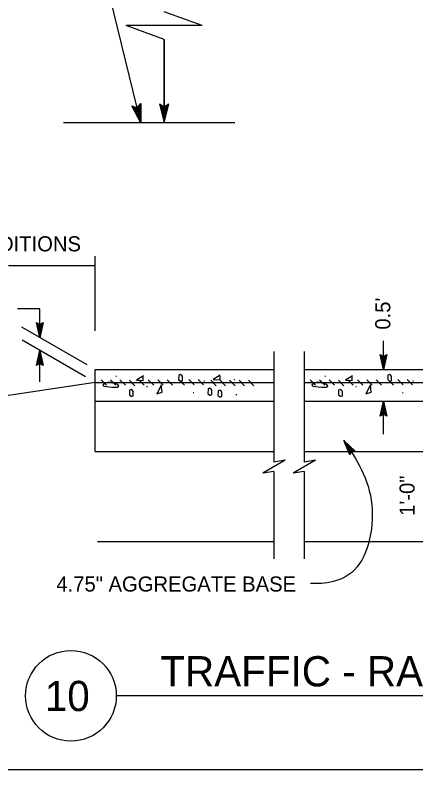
# Model space of a CAD drawing. Extents: x 6710407 to 6714861, y 1868090 to 1871317.
# Drawn here: x 6712808.6 to 6712967.7, y 1869155.1 to 1869454.7 of the extents above; entities that cross this region are included whole.
import ezdxf

# ---------------------------------------------------------------- set-up
doc = ezdxf.new("R2010")
doc.units = 0
for name, color, linetype in [('G-MARK', 7, 'Continuous'), ('G-TEXT', 7, 'Continuous'), ('G-TTLB-VIEW', 7, 'Continuous'), ('Nongeo Data(60)', 7, 'Continuous'), ('Sndwall Anno(59)', 7, 'Continuous')]:
    doc.layers.add(name, color=color, linetype=linetype)

# ---------------------------------------------------------------- blocks, each defined once
blk = doc.blocks.new('SHORTN')
at = {"layer": 'Sndwall Anno(59)'}
for p, q in [((-0.00193, 0), (-0.00259, 0.00447)), ((0.00264, -0.00447), (-0.00259, 0.00447)), ((-0.00193, 0), (-0.00193, 0)), ((0.00264, -0.00447), (0.00183, 0)), ((0.00183, 0), (0.00183, 0))]:
    blk.add_line(p, q, dxfattribs=at)

msp = doc.modelspace()

# ---------------------------------------------------------------- linework, layer by layer
at = {"layer": 'G-MARK'}
for p, q in [((6712858.43, 1869411.94), (6712844.63, 1869468.68)), ((6712882.78, 1869450.55), (6712867.73, 1869456.03)), ((6712882.78, 1869450.55), (6712852.68, 1869450.55)), ((6712867.73, 1869445.07), (6712852.68, 1869450.55)), ((6712867.73, 1869416.44), (6712867.73, 1869445.07)), ((6712895.84, 1869411.94), (6712827.82, 1869411.94)), ((6712840.41, 1869329.3), (6712840.41, 1869359.05)), ((6712805.88, 1869355.31), (6712840.41, 1869355.31)), ((6712818.41, 1869338.16), (6712809.58, 1869338.16)), ((6712818.41, 1869326.65), (6712818.41, 1869338.16)), ((6712837.19, 1869315.81), (6712811.24, 1869330.79)), ((6712836.45, 1869311.13), (6712811.35, 1869325.62)), ((6712954.78, 1869313.95), (6712954.78, 1869325.45)), ((6712818.41, 1869309.17), (6712818.41, 1869321.55)), ((6712911.34, 1869321.18), (6712911.34, 1869277.18)), ((6712923.37, 1869321.18), (6712923.37, 1869277.18)), ((6712954.78, 1869288.32), (6712954.78, 1869301.45)), ((6712911.34, 1869273.48), (6712911.34, 1869238.86)), ((6712923.37, 1869273.48), (6712923.37, 1869238.86)), ((6712841.25, 1869245.76), (6712911.34, 1869245.76)), ((6712923.4, 1869245.76), (6713088.4, 1869245.76))]:
    msp.add_line(p, q, dxfattribs=at)
msp.add_open_spline([(6712939.09, 1869285.79), (6712942.78, 1869280.42), (6712954.02, 1869264.09), (6712946.4, 1869228.42), (6712929.08, 1869228.94), (6712925.89, 1869229.03)], degree=3, dxfattribs=at)
at = {"layer": 'G-TEXT'}
for p, q in [((6712818.41, 1869326.65), (6712817.08, 1869332.65)), ((6712817.08, 1869332.65), (6712817.08, 1869332.65)), ((6712817.08, 1869332.65), (6712818.41, 1869331.85)), ((6712818.4, 1869328.04), (6712817.43, 1869332.42)), ((6712818.41, 1869329.42), (6712817.78, 1869332.24)), ((6712818.41, 1869330.8), (6712818.14, 1869332.01)), ((6712818.41, 1869331.85), (6712819.75, 1869332.65)), ((6712819.75, 1869332.65), (6712818.41, 1869326.65)), ((6712819.39, 1869332.44), (6712818.41, 1869328.03)), ((6712819.03, 1869332.2), (6712818.41, 1869329.42)), ((6712818.68, 1869332.03), (6712818.41, 1869330.8)), ((6712819.75, 1869332.65), (6712819.75, 1869332.65)), ((6712818.41, 1869326.65), (6712818.41, 1869326.65)), ((6712817.07, 1869315.55), (6712818.41, 1869321.55)), ((6712817.42, 1869315.76), (6712818.41, 1869320.17)), ((6712817.78, 1869316), (6712818.4, 1869318.78)), ((6712818.4, 1869318.78), (6712819.03, 1869315.96)), ((6712818.41, 1869321.55), (6712818.41, 1869321.55)), ((6712818.41, 1869321.55), (6712819.74, 1869315.55)), ((6712818.41, 1869320.16), (6712819.38, 1869315.78)), ((6712954.78, 1869313.95), (6712953.45, 1869319.95)), ((6712953.45, 1869319.95), (6712953.45, 1869319.95)), ((6712953.45, 1869319.95), (6712954.78, 1869319.15)), ((6712954.77, 1869315.34), (6712953.81, 1869319.72)), ((6712954.78, 1869316.71), (6712954.15, 1869319.54)), ((6712954.78, 1869318.1), (6712954.51, 1869319.3)), ((6712954.78, 1869319.15), (6712956.12, 1869319.95)), ((6712956.12, 1869319.95), (6712954.78, 1869313.95)), ((6712955.76, 1869319.73), (6712954.78, 1869315.33)), ((6712955.4, 1869319.5), (6712954.78, 1869316.71)), ((6712955.05, 1869319.32), (6712954.78, 1869318.1)), ((6712956.12, 1869319.95), (6712956.12, 1869319.95)), ((6712818.41, 1869316.35), (6712817.07, 1869315.55)), ((6712818.13, 1869316.17), (6712818.4, 1869317.4)), ((6712818.4, 1869317.4), (6712818.67, 1869316.19)), ((6712819.74, 1869315.55), (6712818.41, 1869316.35)), ((6712817.07, 1869315.55), (6712817.07, 1869315.55)), ((6712819.74, 1869315.55), (6712819.74, 1869315.55)), ((6712954.78, 1869313.95), (6712954.78, 1869313.95)), ((6712953.44, 1869295.45), (6712954.78, 1869301.45)), ((6712954.78, 1869301.45), (6712954.78, 1869301.45)), ((6712954.78, 1869301.45), (6712956.11, 1869295.45)), ((6712953.79, 1869295.67), (6712954.78, 1869300.07)), ((6712954.15, 1869295.9), (6712954.77, 1869298.69)), ((6712954.77, 1869298.69), (6712955.4, 1869295.86)), ((6712954.78, 1869300.06), (6712955.75, 1869295.69)), ((6712954.78, 1869296.25), (6712953.44, 1869295.45)), ((6712953.44, 1869295.45), (6712953.44, 1869295.45)), ((6712954.5, 1869296.08), (6712954.77, 1869297.31)), ((6712954.77, 1869297.31), (6712955.04, 1869296.1)), ((6712956.11, 1869295.45), (6712954.78, 1869296.25)), ((6712956.11, 1869295.45), (6712956.11, 1869295.45)), ((6712941.39, 1869280.09), (6712939.09, 1869285.79)), ((6712939.09, 1869285.79), (6712939.09, 1869285.79)), ((6712939.09, 1869285.79), (6712943.59, 1869281.6)), ((6712941.56, 1869280.47), (6712939.87, 1869284.65)), ((6712939.88, 1869284.64), (6712943.16, 1869281.59)), ((6712941.72, 1869280.86), (6712940.65, 1869283.51)), ((6712940.65, 1869283.51), (6712942.77, 1869281.54)), ((6712942.04, 1869281.5), (6712941.39, 1869280.09)), ((6712941.39, 1869280.09), (6712941.39, 1869280.09)), ((6712941.91, 1869281.2), (6712941.44, 1869282.37)), ((6712941.44, 1869282.37), (6712942.34, 1869281.53)), ((6712943.59, 1869281.6), (6712942.04, 1869281.5)), ((6712943.59, 1869281.6), (6712943.59, 1869281.6))]:
    msp.add_line(p, q, dxfattribs=at)
for points in [[(6712858.43, 1869411.94), (6712854.87, 1869418.7), (6712856.97, 1869417.94), (6712858.48, 1869419.58), (6712858.43, 1869411.94)], [(6712858.43, 1869411.94), (6712854.87, 1869418.7), (6712856.97, 1869417.94), (6712858.48, 1869419.58), (6712858.43, 1869411.94)], [(6712858.12, 1869413.22), (6712855.54, 1869418.12), (6712857.06, 1869417.57), (6712858.15, 1869418.75), (6712858.12, 1869413.22)], [(6712858.12, 1869413.22), (6712855.54, 1869418.12), (6712857.06, 1869417.57), (6712858.15, 1869418.75), (6712858.12, 1869413.22)], [(6712857.86, 1869414.29), (6712856.1, 1869417.63), (6712857.14, 1869417.25), (6712857.89, 1869418.06), (6712857.86, 1869414.29)], [(6712857.86, 1869414.29), (6712856.1, 1869417.63), (6712857.14, 1869417.25), (6712857.89, 1869418.06), (6712857.86, 1869414.29)], [(6712867.73, 1869411.94), (6712869.58, 1869419.35), (6712867.73, 1869418.12), (6712865.87, 1869419.35), (6712867.73, 1869411.94)], [(6712867.73, 1869411.94), (6712869.58, 1869419.35), (6712867.73, 1869418.12), (6712865.87, 1869419.35), (6712867.73, 1869411.94)], [(6712867.73, 1869413.25), (6712869.07, 1869418.62), (6712867.73, 1869417.73), (6712866.38, 1869418.62), (6712867.73, 1869413.25)], [(6712867.73, 1869413.25), (6712869.07, 1869418.62), (6712867.73, 1869417.73), (6712866.38, 1869418.62), (6712867.73, 1869413.25)], [(6712867.73, 1869414.36), (6712868.65, 1869418.01), (6712867.73, 1869417.4), (6712866.81, 1869418.01), (6712867.73, 1869414.36)], [(6712867.73, 1869414.36), (6712868.65, 1869418.01), (6712867.73, 1869417.4), (6712866.81, 1869418.01), (6712867.73, 1869414.36)], [(6712857.64, 1869415.17), (6712856.56, 1869417.22), (6712857.2, 1869417), (6712857.66, 1869417.49), (6712857.64, 1869415.17)], [(6712857.64, 1869415.17), (6712856.56, 1869417.22), (6712857.2, 1869417), (6712857.66, 1869417.49), (6712857.64, 1869415.17)], [(6712857.85, 1869415.28), (6712857.05, 1869416.8), (6712857.26, 1869416.72), (6712857.42, 1869416.89), (6712857.4, 1869415.17)], [(6712857.85, 1869415.28), (6712857.05, 1869416.8), (6712857.26, 1869416.72), (6712857.42, 1869416.89), (6712857.4, 1869415.17)], [(6712867.73, 1869415.27), (6712868.3, 1869417.52), (6712867.73, 1869417.15), (6712867.16, 1869417.52), (6712867.73, 1869415.27)], [(6712867.73, 1869415.27), (6712868.3, 1869417.52), (6712867.73, 1869417.15), (6712867.16, 1869417.52), (6712867.73, 1869415.27)], [(6712867.5, 1869415.32), (6712867.92, 1869416.98), (6712867.73, 1869416.86), (6712867.54, 1869416.98), (6712867.96, 1869415.32)], [(6712867.5, 1869415.32), (6712867.92, 1869416.98), (6712867.73, 1869416.86), (6712867.54, 1869416.98), (6712867.96, 1869415.32)]]:
    msp.add_lwpolyline(points, dxfattribs=at)
at = {"layer": 'G-TTLB-VIEW'}
msp.add_lwpolyline([(6711433.78, 1870605.06), (6713227.53, 1870605.06), (6713227.53, 1869155.06), (6711433.78, 1869155.06)], close=True, dxfattribs=at)
at = {"layer": 'Nongeo Data(60)'}
for p, q in [((6712867.73, 1869445.07), (6712867.73, 1869411.94)), ((6712840.41, 1869313.95), (6712911.34, 1869313.95)), ((6712840.41, 1869281.45), (6712840.41, 1869313.95)), ((6712923.4, 1869313.95), (6713088.4, 1869313.95)), ((6712844.83, 1869307.79), (6712842.69, 1869309.93)), ((6712848.58, 1869307.79), (6712846.44, 1869309.93)), ((6712848.54, 1869311.4), (6712848.82, 1869311.4)), ((6712852.33, 1869307.79), (6712850.19, 1869309.93)), ((6712859.83, 1869307.79), (6712857.69, 1869309.93)), ((6712863.58, 1869307.79), (6712861.44, 1869309.93)), ((6712867.33, 1869307.79), (6712865.19, 1869309.93)), ((6712871.08, 1869307.79), (6712868.94, 1869309.93)), ((6712875.86, 1869307.73), (6712873.72, 1869309.87)), ((6712879.61, 1869307.93), (6712877.47, 1869310.07)), ((6712883.36, 1869307.93), (6712881.22, 1869310.07)), ((6712895.47, 1869310.09), (6712895.75, 1869310.09)), ((6712927.83, 1869307.79), (6712925.69, 1869309.93)), ((6712931.58, 1869307.79), (6712929.44, 1869309.93)), ((6712931.53, 1869311.4), (6712931.81, 1869311.4)), ((6712935.33, 1869307.79), (6712933.19, 1869309.93)), ((6712942.83, 1869307.79), (6712940.69, 1869309.93)), ((6712946.58, 1869307.79), (6712944.44, 1869309.93)), ((6712950.33, 1869307.79), (6712948.19, 1869309.93)), ((6712954.08, 1869307.79), (6712951.94, 1869309.93)), ((6712958.85, 1869307.73), (6712956.71, 1869309.87)), ((6712962.6, 1869307.93), (6712960.46, 1869310.07)), ((6712966.35, 1869307.93), (6712964.21, 1869310.07)), ((6712840.37, 1869308.86), (6712755.29, 1869296.08)), ((6712840.37, 1869308.86), (6712911.34, 1869308.86)), ((6712856.08, 1869307.59), (6712853.94, 1869309.73)), ((6712860.79, 1869307.22), (6712861.07, 1869307.22)), ((6712883.48, 1869309.57), (6712883.76, 1869309.57)), ((6712888.37, 1869307.59), (6712886.23, 1869309.73)), ((6712892.12, 1869307.59), (6712889.98, 1869309.73)), ((6712895.87, 1869307.59), (6712893.73, 1869309.73)), ((6712899.62, 1869307.59), (6712897.48, 1869309.73)), ((6712903.37, 1869307.59), (6712901.23, 1869309.73)), ((6712923.37, 1869308.86), (6713088.5, 1869308.86)), ((6712939.08, 1869307.59), (6712936.94, 1869309.73)), ((6712943.79, 1869307.22), (6712944.07, 1869307.22)), ((6712966.47, 1869309.57), (6712966.75, 1869309.57)), ((6712879.3, 1869304.87), (6712879.58, 1869304.87)), ((6712896.25, 1869304.09), (6712896.53, 1869304.09)), ((6712962.3, 1869304.87), (6712962.58, 1869304.87)), ((6712840.41, 1869301.45), (6712911.34, 1869301.45)), ((6712923.4, 1869301.45), (6713088.4, 1869301.45)), ((6712840.41, 1869281.45), (6712911.34, 1869281.45)), ((6712923.4, 1869281.45), (6713088.4, 1869281.45)), ((6713173.03, 1869184.48), (6712848.73, 1869184.48))]:
    msp.add_line(p, q, dxfattribs=at)
for points in [[(6712859.52, 1869311.48), (6712856.72, 1869309.76), (6712859.4, 1869309.64), (6712859.4, 1869311.15)], [(6712873.53, 1869311.52), (6712873.47, 1869309.99), (6712874.19, 1869309.37), (6712874.54, 1869309.37), (6712875.04, 1869309.55), (6712875.04, 1869310.27), (6712875.04, 1869311.23), (6712874.76, 1869311.68), (6712874.14, 1869312.06), (6712873.53, 1869311.79), (6712873.53, 1869311.52), (6712873.53, 1869311.52)], [(6712890.03, 1869311.74), (6712887.23, 1869310.02), (6712889.91, 1869309.9), (6712889.91, 1869311.41)], [(6712942.52, 1869311.48), (6712939.72, 1869309.76), (6712942.4, 1869309.64), (6712942.4, 1869311.15)], [(6712956.53, 1869311.52), (6712956.47, 1869309.99), (6712957.19, 1869309.37), (6712957.54, 1869309.37), (6712958.04, 1869309.55), (6712958.04, 1869310.27), (6712958.04, 1869311.23), (6712957.76, 1869311.68), (6712957.14, 1869312.06), (6712956.53, 1869311.79), (6712956.53, 1869311.52), (6712956.53, 1869311.52)], [(6712847.19, 1869308.81), (6712845.78, 1869308.98), (6712844.16, 1869308.47), (6712843.33, 1869307.85), (6712843.78, 1869307.36), (6712845.91, 1869307.07), (6712847.19, 1869306.96), (6712849.03, 1869307.01), (6712849.71, 1869307.36), (6712849.37, 1869308.08), (6712848.43, 1869308.26), (6712847.08, 1869308.69), (6712847.08, 1869308.69)], [(6712866.5, 1869307.7), (6712864.82, 1869304.34), (6712866.95, 1869305.01), (6712866.61, 1869307.97)], [(6712930.19, 1869308.81), (6712928.78, 1869308.98), (6712927.16, 1869308.47), (6712926.33, 1869307.85), (6712926.78, 1869307.36), (6712928.91, 1869307.07), (6712930.19, 1869306.96), (6712932.03, 1869307.01), (6712932.71, 1869307.36), (6712932.37, 1869308.08), (6712931.43, 1869308.26), (6712930.08, 1869308.69), (6712930.08, 1869308.69)], [(6712949.5, 1869307.7), (6712947.82, 1869304.34), (6712949.95, 1869305.01), (6712949.61, 1869307.97)], [(6712853.98, 1869305.52), (6712853.92, 1869303.99), (6712854.64, 1869303.37), (6712854.99, 1869303.37), (6712855.49, 1869303.55), (6712855.49, 1869304.27), (6712855.49, 1869305.23), (6712855.21, 1869305.68), (6712854.59, 1869306.06), (6712853.98, 1869305.79), (6712853.98, 1869305.52), (6712853.98, 1869305.52)], [(6712885.17, 1869306.04), (6712885.11, 1869304.51), (6712885.83, 1869303.89), (6712886.18, 1869303.89), (6712886.68, 1869304.07), (6712886.68, 1869304.79), (6712886.68, 1869305.75), (6712886.4, 1869306.2), (6712885.78, 1869306.58), (6712885.17, 1869306.31), (6712885.17, 1869306.04), (6712885.17, 1869306.04)], [(6712889.17, 1869305.26), (6712889.11, 1869303.73), (6712889.83, 1869303.11), (6712890.18, 1869303.11), (6712890.68, 1869303.29), (6712890.68, 1869304.01), (6712890.68, 1869304.97), (6712890.4, 1869305.42), (6712889.78, 1869305.8), (6712889.17, 1869305.53), (6712889.17, 1869305.26), (6712889.17, 1869305.26)], [(6712936.97, 1869305.52), (6712936.91, 1869303.99), (6712937.63, 1869303.37), (6712937.98, 1869303.37), (6712938.48, 1869303.55), (6712938.48, 1869304.27), (6712938.48, 1869305.23), (6712938.2, 1869305.68), (6712937.58, 1869306.06), (6712936.97, 1869305.79), (6712936.97, 1869305.52), (6712936.97, 1869305.52)]]:
    msp.add_lwpolyline(points, dxfattribs=at)
msp.add_circle((6712830.73, 1869184.48), 18, dxfattribs=at)

# ---------------------------------------------------------------- block references
at = {"layer": 'G-MARK', "xscale": 984.251968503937, "yscale": 984.251968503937, "rotation": 90}
for p in [(6712911.34, 1869275.39), (6712923.37, 1869275.39)]:
    msp.add_blockref('SHORTN', p, dxfattribs=at)

# ---------------------------------------------------------------- texts
at = {"layer": 'Nongeo Data(60)'}
for s, height, p in [('UNPAVED CONDITIONS', 6, (6712743.33, 1869360.91)), ('4.75" AGGREGATE BASE', 6, (6712824.96, 1869225.86)), ('TRAFFIC - RATED SIDEWALK', 12, (6712866.22, 1869188.22)), ('10', 12, (6712820.35, 1869178.42))]:
    msp.add_text(s, height=height, dxfattribs=at).set_placement(p)
for s, p in [("0.5'", (6712957.53, 1869329.84)), ('1\'-0"', (6712967.17, 1869255.93))]:
    msp.add_text(s, height=6, rotation=90, dxfattribs=at).set_placement(p)

doc.saveas('drawing.dxf')
